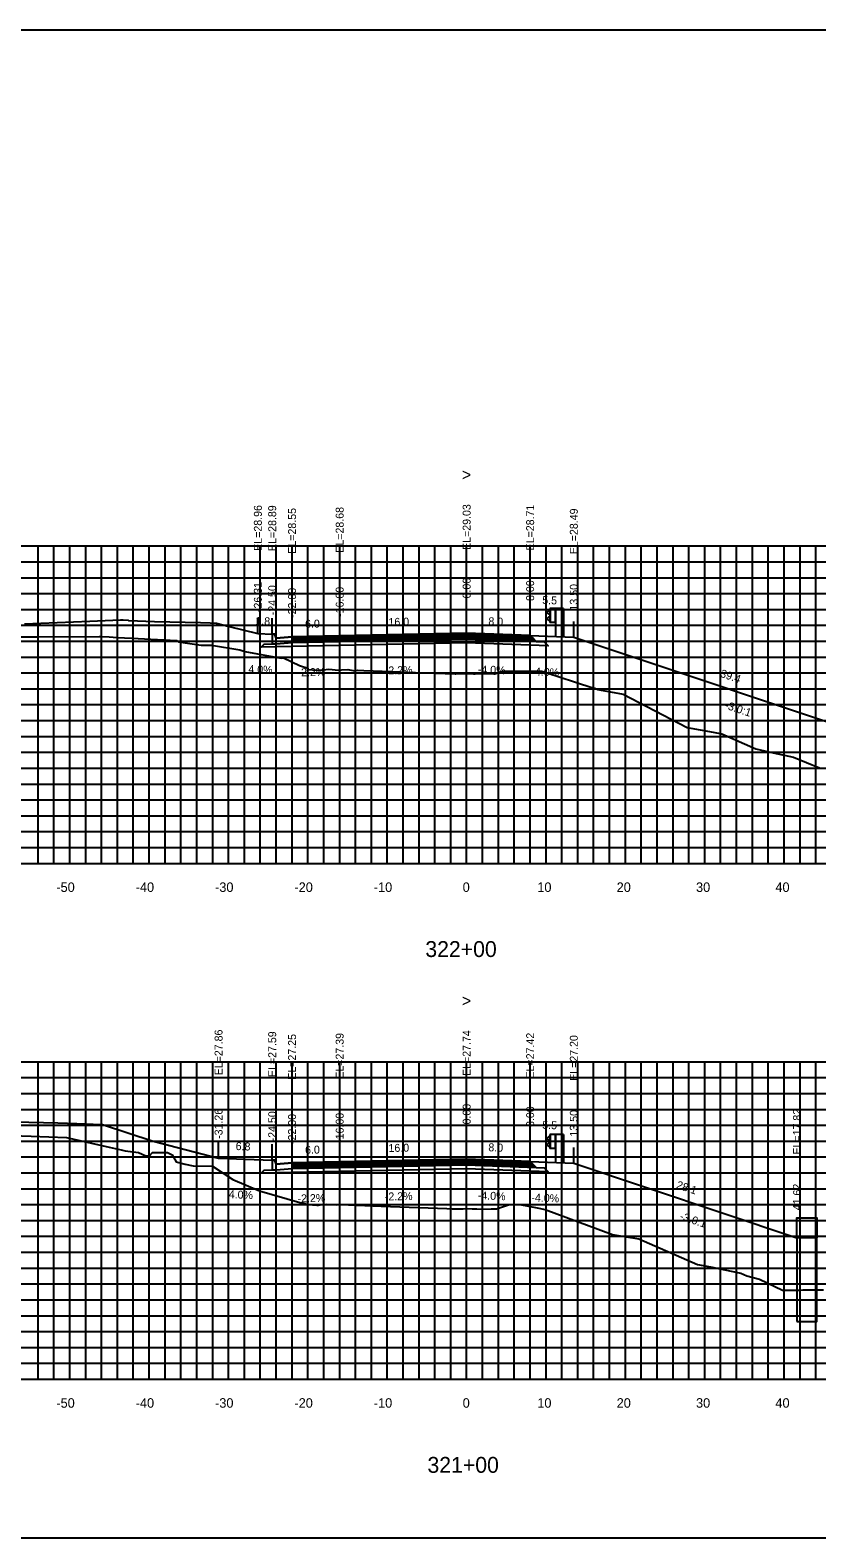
# Model space of a CAD drawing. Extents: x 1797652 to 1804145, y 245981 to 250269.
# Drawn here: x 1803256 to 1803355.1, y 250079.4 to 250269.4 of the extents above; entities that cross this region are included whole.
import ezdxf

# ---------------------------------------------------------------- set-up
doc = ezdxf.new("R2010")
doc.units = 0
for name, color, linetype in [('1', 7, 'Continuous'), ('10', 7, 'Continuous'), ('3', 7, 'Continuous'), ('4', 7, 'Continuous'), ('60', 7, 'Continuous'), ('BASE', 7, 'Continuous'), ('CL-CNST', 7, 'Continuous'), ('Level 1', 7, 'Continuous'), ('Level 62', 7, 'Continuous'), ('LOWER BINDER', 7, 'Continuous'), ('M-ROADS', 7, 'Continuous'), ('UPPER BINDER', 7, 'Continuous'), ('WEARING', 7, 'Continuous')]:
    doc.layers.add(name, color=color, linetype=linetype)

msp = doc.modelspace()

# ---------------------------------------------------------------- linework, layer by layer
for p, q in [((1803284.69, 250193.39), (1803284.69, 250195.39)), ((1803286.5, 250193.32), (1803286.5, 250195.32)), ((1803289, 250192.98), (1803289, 250194.98)), ((1803295, 250193.11), (1803295, 250195.11)), ((1803311, 250193.46), (1803311, 250195.46)), ((1803319, 250193.14), (1803319, 250195.14)), ((1803324.5, 250192.92), (1803324.5, 250194.92)), ((1803279.74, 250127.3), (1803279.74, 250129.3)), ((1803286.5, 250127.03), (1803286.5, 250129.03)), ((1803289, 250126.69), (1803289, 250128.69)), ((1803295, 250126.82), (1803295, 250128.82)), ((1803311, 250127.17), (1803311, 250129.17)), ((1803319, 250126.85), (1803319, 250128.85)), ((1803324.5, 250126.63), (1803324.5, 250128.63)), ((1803352.62, 250117.26), (1803352.62, 250119.26))]:
    msp.add_line(p, q)
for points in [[(1803161, 250079.43), (1803461, 250079.43), (1803461, 250269.43), (1803161, 250269.43)], [(1803289, 250192.98), (1803287, 250192.82), (1803286.83, 250193.32), (1803286.5, 250193.32), (1803286.5, 250192.1), (1803287, 250192.1), (1803289, 250192.26)], [(1803289, 250126.69), (1803287, 250126.53), (1803286.83, 250127.03), (1803286.5, 250127.03), (1803286.5, 250125.81), (1803287, 250125.81), (1803289, 250125.97)]]:
    msp.add_lwpolyline(points, close=True)
at = {"layer": '60'}
for p, q in [((1803161, 250164.43), (1803461, 250164.43)), ((1803261, 250164.37), (1803261, 250164.43)), ((1803271, 250164.37), (1803271, 250164.43)), ((1803281, 250164.37), (1803281, 250164.43)), ((1803291, 250164.37), (1803291, 250164.43)), ((1803301, 250164.37), (1803301, 250164.43)), ((1803311, 250164.37), (1803311, 250164.43)), ((1803321, 250164.37), (1803321, 250164.43)), ((1803331, 250164.37), (1803331, 250164.43)), ((1803341, 250164.37), (1803341, 250164.43)), ((1803351, 250164.37), (1803351, 250164.43)), ((1803161, 250099.43), (1803461, 250099.43)), ((1803261, 250099.37), (1803261, 250099.43)), ((1803271, 250099.37), (1803271, 250099.43)), ((1803281, 250099.37), (1803281, 250099.43)), ((1803291, 250099.37), (1803291, 250099.43)), ((1803301, 250099.37), (1803301, 250099.43)), ((1803311, 250099.37), (1803311, 250099.43)), ((1803321, 250099.37), (1803321, 250099.43)), ((1803331, 250099.37), (1803331, 250099.43)), ((1803341, 250099.37), (1803341, 250099.43)), ((1803351, 250099.37), (1803351, 250099.43))]:
    msp.add_line(p, q, dxfattribs=at)
at = {"layer": 'BASE'}
for points in [[(1803289, 250192.26), (1803295, 250192.39), (1803311, 250192.74), (1803319.75, 250192.39), (1803320.75, 250192.35), (1803321.27, 250191.83), (1803311, 250192.24), (1803295, 250191.89), (1803289, 250191.76), (1803285.09, 250191.67), (1803285.5, 250192.07), (1803286.5, 250192.1), (1803287, 250192.1)], [(1803289, 250125.97), (1803295, 250126.1), (1803311, 250126.45), (1803319.75, 250126.1), (1803320.75, 250126.06), (1803321.27, 250125.54), (1803311, 250125.95), (1803295, 250125.6), (1803289, 250125.47), (1803285.09, 250125.38), (1803285.5, 250125.78), (1803286.5, 250125.81), (1803287, 250125.81)]]:
    msp.add_lwpolyline(points, close=True, dxfattribs=at)
at = {"layer": 'CL-CNST'}
for points in [[(1803255.27, 250194.6), (1803263.52, 250194.95), (1803267.37, 250195.12), (1803267.71, 250195.1), (1803268.37, 250195.08), (1803268.41, 250195.04), (1803268.43, 250195.02), (1803271.66, 250194.93), (1803277.45, 250194.78), (1803278.67, 250194.73), (1803279.47, 250194.7), (1803281.09, 250194.29), (1803284.69, 250193.39)], [(1803284.69, 250193.39), (1803286.5, 250193.32), (1803286.83, 250193.32), (1803287, 250192.82), (1803289, 250192.98), (1803295, 250193.11), (1803311, 250193.46), (1803319, 250193.14), (1803324.5, 250192.92), (1803363.91, 250179.78)], [(1803254.03, 250131.86), (1803259.49, 250131.72), (1803263.09, 250131.62), (1803263.95, 250131.58), (1803265.11, 250131.53), (1803271.51, 250129.41), (1803279.74, 250127.3)], [(1803279.74, 250127.3), (1803286.5, 250127.03), (1803286.83, 250127.03), (1803287, 250126.53), (1803289, 250126.69), (1803295, 250126.82), (1803311, 250127.17), (1803319, 250126.85), (1803324.5, 250126.63), (1803352.62, 250117.26)]]:
    msp.add_lwpolyline(points, dxfattribs=at)
for points in [[(1803355.12, 250117.26), (1803352.62, 250117.26), (1803352.62, 250119.76), (1803355.12, 250119.76)], [(1803352.62, 250106.68), (1803355.12, 250106.68), (1803355.12, 250117.26), (1803352.62, 250117.26)]]:
    msp.add_lwpolyline(points, close=True, dxfattribs=at)
at = {"layer": 'Level 1'}
for p, q in [((1803321.46, 250196.39), (1803321.1, 250196.09)), ((1803321.1, 250196.02), (1803321.46, 250195.73)), ((1803321.46, 250196.54), (1803321.46, 250194.79)), ((1803323.21, 250196.54), (1803321.46, 250196.54)), ((1803321.51, 250196.54), (1803321.51, 250194.79)), ((1803322.16, 250196.54), (1803322.16, 250194.79)), ((1803322.21, 250196.54), (1803322.21, 250193.01)), ((1803323.21, 250196.54), (1803323.21, 250192.97)), ((1803321.46, 250195.59), (1803321.1, 250195.29)), ((1803321.1, 250195.22), (1803321.46, 250194.94)), ((1803322.21, 250194.79), (1803321.46, 250194.79)), ((1803321.46, 250130.1), (1803321.1, 250129.8)), ((1803321.1, 250129.73), (1803321.46, 250129.44)), ((1803321.46, 250129.3), (1803321.1, 250129)), ((1803321.46, 250130.25), (1803321.46, 250128.5)), ((1803323.21, 250130.25), (1803321.46, 250130.25)), ((1803321.51, 250130.25), (1803321.51, 250128.5)), ((1803322.16, 250130.25), (1803322.16, 250128.5)), ((1803322.21, 250130.25), (1803322.21, 250126.72)), ((1803323.21, 250130.25), (1803323.21, 250126.68)), ((1803321.1, 250128.93), (1803321.46, 250128.65)), ((1803322.21, 250128.5), (1803321.46, 250128.5))]:
    msp.add_line(p, q, dxfattribs=at)
for centre in [(1803321.13, 250196.05), (1803321.13, 250195.26), (1803321.13, 250129.76), (1803321.13, 250128.97)]:
    msp.add_arc(centre, 0.05, 135, 226.6208, dxfattribs=at)
at = {"layer": 'Level 62'}
for p, q in [((1803161, 250204.43), (1803461, 250204.43)), ((1803257, 250164.43), (1803257, 250204.43)), ((1803259, 250164.43), (1803259, 250204.43)), ((1803261, 250164.43), (1803261, 250204.43)), ((1803263, 250164.43), (1803263, 250204.43)), ((1803265, 250164.43), (1803265, 250204.43)), ((1803267, 250164.43), (1803267, 250204.43)), ((1803269, 250164.43), (1803269, 250204.43)), ((1803271, 250164.43), (1803271, 250204.43)), ((1803273, 250164.43), (1803273, 250204.43)), ((1803275, 250164.43), (1803275, 250204.43)), ((1803277, 250164.43), (1803277, 250204.43)), ((1803279, 250164.43), (1803279, 250204.43)), ((1803281, 250164.43), (1803281, 250204.43)), ((1803283, 250164.43), (1803283, 250204.43)), ((1803285, 250164.43), (1803285, 250204.43)), ((1803287, 250164.43), (1803287, 250204.43)), ((1803289, 250164.43), (1803289, 250204.43)), ((1803291, 250164.43), (1803291, 250204.43)), ((1803293, 250164.43), (1803293, 250204.43)), ((1803295, 250164.43), (1803295, 250204.43)), ((1803297, 250164.43), (1803297, 250204.43)), ((1803299, 250164.43), (1803299, 250204.43)), ((1803301, 250164.43), (1803301, 250204.43)), ((1803303, 250164.43), (1803303, 250204.43)), ((1803305, 250164.43), (1803305, 250204.43)), ((1803307, 250164.43), (1803307, 250204.43)), ((1803309, 250164.43), (1803309, 250204.43)), ((1803311, 250164.43), (1803311, 250204.43)), ((1803313, 250164.43), (1803313, 250204.43)), ((1803315, 250164.43), (1803315, 250204.43)), ((1803317, 250164.43), (1803317, 250204.43)), ((1803319, 250164.43), (1803319, 250204.43)), ((1803321, 250164.43), (1803321, 250204.43)), ((1803323, 250164.43), (1803323, 250204.43)), ((1803325, 250164.43), (1803325, 250204.43)), ((1803327, 250164.43), (1803327, 250204.43)), ((1803329, 250164.43), (1803329, 250204.43)), ((1803331, 250164.43), (1803331, 250204.43)), ((1803333, 250164.43), (1803333, 250204.43)), ((1803335, 250164.43), (1803335, 250204.43)), ((1803337, 250164.43), (1803337, 250204.43)), ((1803339, 250164.43), (1803339, 250204.43)), ((1803341, 250164.43), (1803341, 250204.43)), ((1803343, 250164.43), (1803343, 250204.43)), ((1803345, 250164.43), (1803345, 250204.43)), ((1803347, 250164.43), (1803347, 250204.43)), ((1803349, 250164.43), (1803349, 250204.43)), ((1803351, 250164.43), (1803351, 250204.43)), ((1803353, 250164.43), (1803353, 250204.43)), ((1803355, 250164.43), (1803355, 250204.43)), ((1803161, 250202.43), (1803461, 250202.43)), ((1803161, 250200.43), (1803461, 250200.43)), ((1803161, 250198.43), (1803461, 250198.43)), ((1803161, 250196.43), (1803461, 250196.43)), ((1803161, 250194.43), (1803461, 250194.43)), ((1803161, 250192.43), (1803461, 250192.43)), ((1803161, 250190.43), (1803461, 250190.43)), ((1803161, 250188.43), (1803461, 250188.43)), ((1803161, 250186.43), (1803461, 250186.43)), ((1803161, 250184.43), (1803461, 250184.43)), ((1803161, 250182.43), (1803461, 250182.43)), ((1803161, 250180.43), (1803461, 250180.43)), ((1803161, 250178.43), (1803461, 250178.43)), ((1803161, 250176.43), (1803461, 250176.43)), ((1803161, 250174.43), (1803461, 250174.43)), ((1803161, 250172.43), (1803461, 250172.43)), ((1803161, 250170.43), (1803461, 250170.43)), ((1803161, 250168.43), (1803461, 250168.43)), ((1803161, 250166.43), (1803461, 250166.43)), ((1803161, 250164.43), (1803461, 250164.43)), ((1803161, 250139.43), (1803461, 250139.43)), ((1803257, 250099.43), (1803257, 250139.43)), ((1803259, 250099.43), (1803259, 250139.43)), ((1803261, 250099.43), (1803261, 250139.43)), ((1803263, 250099.43), (1803263, 250139.43)), ((1803265, 250099.43), (1803265, 250139.43)), ((1803267, 250099.43), (1803267, 250139.43)), ((1803269, 250099.43), (1803269, 250139.43)), ((1803271, 250099.43), (1803271, 250139.43)), ((1803273, 250099.43), (1803273, 250139.43)), ((1803275, 250099.43), (1803275, 250139.43)), ((1803277, 250099.43), (1803277, 250139.43)), ((1803279, 250099.43), (1803279, 250139.43)), ((1803281, 250099.43), (1803281, 250139.43)), ((1803283, 250099.43), (1803283, 250139.43)), ((1803285, 250099.43), (1803285, 250139.43)), ((1803287, 250099.43), (1803287, 250139.43)), ((1803289, 250099.43), (1803289, 250139.43)), ((1803291, 250099.43), (1803291, 250139.43)), ((1803293, 250099.43), (1803293, 250139.43)), ((1803295, 250099.43), (1803295, 250139.43)), ((1803297, 250099.43), (1803297, 250139.43)), ((1803299, 250099.43), (1803299, 250139.43)), ((1803301, 250099.43), (1803301, 250139.43)), ((1803303, 250099.43), (1803303, 250139.43)), ((1803305, 250099.43), (1803305, 250139.43)), ((1803307, 250099.43), (1803307, 250139.43)), ((1803309, 250099.43), (1803309, 250139.43)), ((1803311, 250099.43), (1803311, 250139.43)), ((1803313, 250099.43), (1803313, 250139.43)), ((1803315, 250099.43), (1803315, 250139.43)), ((1803317, 250099.43), (1803317, 250139.43)), ((1803319, 250099.43), (1803319, 250139.43)), ((1803321, 250099.43), (1803321, 250139.43)), ((1803323, 250099.43), (1803323, 250139.43)), ((1803325, 250099.43), (1803325, 250139.43)), ((1803327, 250099.43), (1803327, 250139.43)), ((1803329, 250099.43), (1803329, 250139.43)), ((1803331, 250099.43), (1803331, 250139.43)), ((1803333, 250099.43), (1803333, 250139.43)), ((1803335, 250099.43), (1803335, 250139.43)), ((1803337, 250099.43), (1803337, 250139.43)), ((1803339, 250099.43), (1803339, 250139.43)), ((1803341, 250099.43), (1803341, 250139.43)), ((1803343, 250099.43), (1803343, 250139.43)), ((1803345, 250099.43), (1803345, 250139.43)), ((1803347, 250099.43), (1803347, 250139.43)), ((1803349, 250099.43), (1803349, 250139.43)), ((1803351, 250099.43), (1803351, 250139.43)), ((1803353, 250099.43), (1803353, 250139.43)), ((1803355, 250099.43), (1803355, 250139.43)), ((1803161, 250137.43), (1803461, 250137.43)), ((1803161, 250135.43), (1803461, 250135.43)), ((1803161, 250133.43), (1803461, 250133.43)), ((1803161, 250131.43), (1803461, 250131.43)), ((1803161, 250129.43), (1803461, 250129.43)), ((1803161, 250127.43), (1803461, 250127.43)), ((1803161, 250125.43), (1803461, 250125.43)), ((1803161, 250123.43), (1803461, 250123.43)), ((1803161, 250121.43), (1803461, 250121.43)), ((1803161, 250119.43), (1803461, 250119.43)), ((1803161, 250117.43), (1803461, 250117.43)), ((1803161, 250115.43), (1803461, 250115.43)), ((1803161, 250113.43), (1803461, 250113.43)), ((1803161, 250111.43), (1803461, 250111.43)), ((1803161, 250109.43), (1803461, 250109.43)), ((1803161, 250107.43), (1803461, 250107.43)), ((1803161, 250105.43), (1803461, 250105.43)), ((1803161, 250103.43), (1803461, 250103.43)), ((1803161, 250101.43), (1803461, 250101.43)), ((1803161, 250099.43), (1803461, 250099.43))]:
    msp.add_line(p, q, dxfattribs=at)
at = {"layer": 'LOWER BINDER'}
for points in [[(1803295, 250192.77), (1803311, 250193.12), (1803319.36, 250192.79), (1803319.55, 250192.59), (1803311, 250192.93), (1803295, 250192.58), (1803289, 250192.45), (1803289, 250192.64)], [(1803295, 250192.58), (1803311, 250192.93), (1803319.55, 250192.59), (1803319.75, 250192.39), (1803311, 250192.74), (1803295, 250192.39), (1803289, 250192.26), (1803289, 250192.45)], [(1803295, 250126.48), (1803311, 250126.83), (1803319.36, 250126.5), (1803319.55, 250126.3), (1803311, 250126.64), (1803295, 250126.29), (1803289, 250126.16), (1803289, 250126.35)], [(1803295, 250126.29), (1803311, 250126.64), (1803319.55, 250126.3), (1803319.75, 250126.1), (1803311, 250126.45), (1803295, 250126.1), (1803289, 250125.97), (1803289, 250126.16)]]:
    msp.add_lwpolyline(points, close=True, dxfattribs=at)
at = {"layer": 'M-ROADS'}
for points in [[(1803252.7, 250192.96), (1803257.09, 250192.98), (1803264.71, 250193.01), (1803265.01, 250193), (1803265.96, 250192.96), (1803266.97, 250192.91), (1803268.81, 250192.81), (1803274.42, 250192.5), (1803274.71, 250192.35), (1803277.53, 250191.93), (1803278.21, 250191.93), (1803278.84, 250191.93), (1803282.44, 250191.32), (1803283.07, 250191.14), (1803287.61, 250190.29), (1803287.92, 250190.32), (1803289.92, 250189.37), (1803290.98, 250189.04), (1803291.01, 250188.87), (1803292.1, 250188.78), (1803292.22, 250188.78), (1803292.26, 250188.76), (1803292.49, 250188.77), (1803293, 250188.84), (1803293.57, 250188.89), (1803294.05, 250188.85), (1803294.82, 250188.77), (1803295.24, 250188.81), (1803296.01, 250188.87), (1803296.9, 250188.71), (1803296.92, 250188.71), (1803297.26, 250188.76), (1803298.03, 250188.73), (1803301.54, 250188.62), (1803304.55, 250188.49), (1803308.31, 250188.36), (1803309.54, 250188.3), (1803309.56, 250188.3), (1803309.59, 250188.3), (1803309.63, 250188.31), (1803310.82, 250188.37), (1803311.86, 250188.32), (1803312.07, 250188.31), (1803312.99, 250188.35), (1803313.31, 250188.36), (1803314.44, 250188.3), (1803314.56, 250188.3), (1803315.1, 250188.51), (1803315.41, 250188.63), (1803315.57, 250188.65), (1803317.96, 250188.65), (1803317.97, 250188.65), (1803319.41, 250188.65), (1803320.43, 250188.65), (1803320.46, 250188.65), (1803326.91, 250186.54), (1803327.14, 250186.52), (1803327.51, 250186.32), (1803327.75, 250186.28), (1803330.7, 250185.77), (1803338.78, 250181.56), (1803342.06, 250180.97), (1803343.14, 250180.77), (1803347.42, 250178.87), (1803349.62, 250178.38), (1803352.2, 250177.82), (1803355.44, 250176.49)], [(1803253.7, 250130.15), (1803256.11, 250130.06), (1803260.6, 250129.89), (1803265.95, 250128.67), (1803267.48, 250128.32), (1803267.99, 250128.21), (1803269.64, 250127.98), (1803270.56, 250127.58), (1803271.02, 250127.59), (1803271.41, 250127.98), (1803273.29, 250127.98), (1803273.91, 250127.68), (1803274.4, 250126.82), (1803275.55, 250126.54), (1803276.52, 250126.3), (1803276.57, 250126.31), (1803278.99, 250126.27), (1803281.53, 250124.6), (1803284.88, 250123.16), (1803289.97, 250121.7), (1803290.6, 250121.56), (1803290.86, 250121.44), (1803291.01, 250121.42), (1803292.11, 250121.34), (1803292.32, 250121.34), (1803292.75, 250121.43), (1803293.4, 250121.48), (1803293.96, 250121.44), (1803294.65, 250121.39), (1803295.16, 250121.42), (1803295.86, 250121.43), (1803296.1, 250121.41), (1803297.11, 250121.34), (1803300.22, 250121.23), (1803308.52, 250120.95), (1803309.17, 250120.91), (1803309.77, 250120.88), (1803310.57, 250120.88), (1803311.02, 250120.93), (1803311.7, 250120.9), (1803312.27, 250120.88), (1803312.9, 250120.86), (1803312.94, 250120.86), (1803312.99, 250120.86), (1803314.07, 250120.91), (1803314.77, 250120.88), (1803315.41, 250121.1), (1803316.38, 250121.45), (1803317.7, 250121.45), (1803319.89, 250121.01), (1803320.9, 250120.81), (1803329.39, 250117.66), (1803330.9, 250117.42), (1803332.69, 250117.13), (1803340.1, 250113.9), (1803341.71, 250113.57), (1803345.54, 250112.79), (1803346.32, 250112.46), (1803347.9, 250112.05), (1803350.81, 250110.66), (1803352.91, 250110.66), (1803353.36, 250110.68), (1803354.22, 250110.68), (1803355.94, 250110.68)]]:
    msp.add_lwpolyline(points, dxfattribs=at)
at = {"layer": 'UPPER BINDER'}
for points in [[(1803319.36, 250192.79), (1803319.16, 250192.98), (1803311, 250193.31), (1803295, 250192.96), (1803289, 250192.83), (1803289, 250192.64), (1803295, 250192.77), (1803311, 250193.12)], [(1803319.36, 250126.5), (1803319.16, 250126.69), (1803311, 250127.02), (1803295, 250126.67), (1803289, 250126.54), (1803289, 250126.35), (1803295, 250126.48), (1803311, 250126.83)]]:
    msp.add_lwpolyline(points, close=True, dxfattribs=at)
at = {"layer": 'WEARING'}
for points in [[(1803319.16, 250192.98), (1803319, 250193.14), (1803311, 250193.46), (1803295, 250193.11), (1803289, 250192.98), (1803289, 250192.83), (1803295, 250192.96), (1803311, 250193.31)], [(1803319.16, 250126.69), (1803319, 250126.85), (1803311, 250127.17), (1803295, 250126.82), (1803289, 250126.69), (1803289, 250126.54), (1803295, 250126.67), (1803311, 250127.02)]]:
    msp.add_lwpolyline(points, close=True, dxfattribs=at)

# ---------------------------------------------------------------- texts
for p in [(1803343.42, 250183.98), (1803337.77, 250119.57)]:
    msp.add_text('-3.0:1', height=1, rotation=341.5652).set_placement(p)
at = {"layer": '1'}
for s, p in [('322+00', (1803305.79, 250152.63)), ('321+00', (1803306.06, 250087.63))]:
    msp.add_text(s, height=2, dxfattribs=at).set_placement(p)
at = {"layer": '10'}
for s, p in [('-50', (1803259.3, 250160.83)), ('-40', (1803269.3, 250160.83)), ('-30', (1803279.3, 250160.83)), ('-20', (1803289.3, 250160.83)), ('-10', (1803299.3, 250160.83)), ('0', (1803310.5, 250160.83)), ('10', (1803319.9, 250160.83)), ('20', (1803329.9, 250160.83)), ('30', (1803339.9, 250160.83)), ('40', (1803349.9, 250160.83)), ('-50', (1803259.3, 250095.83)), ('-40', (1803269.3, 250095.83)), ('-30', (1803279.3, 250095.83)), ('-20', (1803289.3, 250095.83)), ('-10', (1803299.3, 250095.83)), ('0', (1803310.5, 250095.83)), ('10', (1803319.9, 250095.83)), ('20', (1803329.9, 250095.83)), ('30', (1803339.9, 250095.83)), ('40', (1803349.9, 250095.83))]:
    msp.add_text(s, height=1.2, dxfattribs=at).set_placement(p)
at = {"layer": '3'}
for s, p in [('EL=28.96', (1803285.19, 250203.82)), ('EL=28.89', (1803287, 250203.79)), ('EL=28.55', (1803289.5, 250203.45)), ('EL=28.68', (1803295.5, 250203.58)), ('EL=29.03', (1803311.5, 250203.93)), ('EL=28.71', (1803319.5, 250203.87)), ('EL=28.49', (1803325, 250203.39)), ('-26.31', (1803285.19, 250196.1)), ('0.00', (1803311.5, 250197.82)), ('8.00', (1803319.5, 250197.5)), ('-24.50', (1803287, 250195.7)), ('-22.00', (1803289.5, 250195.36)), ('-16.00', (1803295.5, 250195.49)), ('13.50', (1803325, 250196.29)), ('EL=27.86', (1803280.24, 250137.72)), ('EL=27.59', (1803287, 250137.5)), ('EL=27.25', (1803289.5, 250137.16)), ('EL=27.39', (1803295.5, 250137.29)), ('EL=27.74', (1803311.5, 250137.64)), ('EL=27.42', (1803319.5, 250137.32)), ('EL=27.20', (1803325, 250137.02)), ('-31.26', (1803280.24, 250129.71)), ('-24.50', (1803287, 250129.4)), ('0.00', (1803311.5, 250131.53)), ('8.00', (1803319.5, 250131.21)), ('13.50', (1803325, 250130)), ('EL=17.82', (1803353.12, 250127.73)), ('-22.00', (1803289.5, 250129.06)), ('-16.00', (1803295.5, 250129.2)), ('41.62', (1803353.12, 250120.71))]:
    msp.add_text(s, height=1, rotation=90, dxfattribs=at).set_placement(p)
at = {"layer": '4'}
for s, rotation, p in [('5.5', 357.7094, (1803320.51, 250197.13)), ('1.8', 357.7094, (1803284.36, 250194.5)), ('6.0', 1.2603, (1803290.65, 250194.11)), ('16.0', 1.2603, (1803301.16, 250194.34)), ('8.0', 357.7094, (1803313.72, 250194.45)), ('4.0%', 357.7094, (1803283.48, 250188.43)), ('-2.2%', 1.2603, (1803289.7, 250187.99)), ('-2.2%', 1.2603, (1803300.7, 250188.23)), ('-4.0%', 357.7094, (1803312.39, 250188.4)), ('-4.0%', 357.7094, (1803319.14, 250188.13)), ('39.4', 341.5652, (1803342.87, 250187.96)), ('5.5', 357.7094, (1803320.51, 250130.99)), ('6.8', 357.7094, (1803281.88, 250128.31)), ('6.0', 1.2603, (1803290.65, 250127.82)), ('16.0', 1.2603, (1803301.16, 250128.05)), ('8.0', 357.7094, (1803313.72, 250128.16)), ('28.1', 341.5652, (1803337.34, 250123.51)), ('4.0%', 357.7094, (1803281.01, 250122.24)), ('-2.2%', 1.2603, (1803289.7, 250121.7)), ('-2.2%', 1.2603, (1803300.7, 250121.94)), ('-4.0%', 357.7094, (1803312.39, 250122.11)), ('-4.0%', 357.7094, (1803319.14, 250121.84))]:
    msp.add_text(s, height=1, rotation=rotation, dxfattribs=at).set_placement(p)
at = {"layer": '60'}
for p in [(1803310.39, 250212.67), (1803310.39, 250146.38)]:
    msp.add_text('>', height=1.5, dxfattribs=at).set_placement(p)

doc.saveas('drawing.dxf')
